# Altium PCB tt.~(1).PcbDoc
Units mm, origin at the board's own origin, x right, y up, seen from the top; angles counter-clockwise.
Board outline 69.6 x 32 mm, 2 copper layers (Top Layer, Bottom Layer); 13 components, 13 nets, 40 pads, 0 vias.
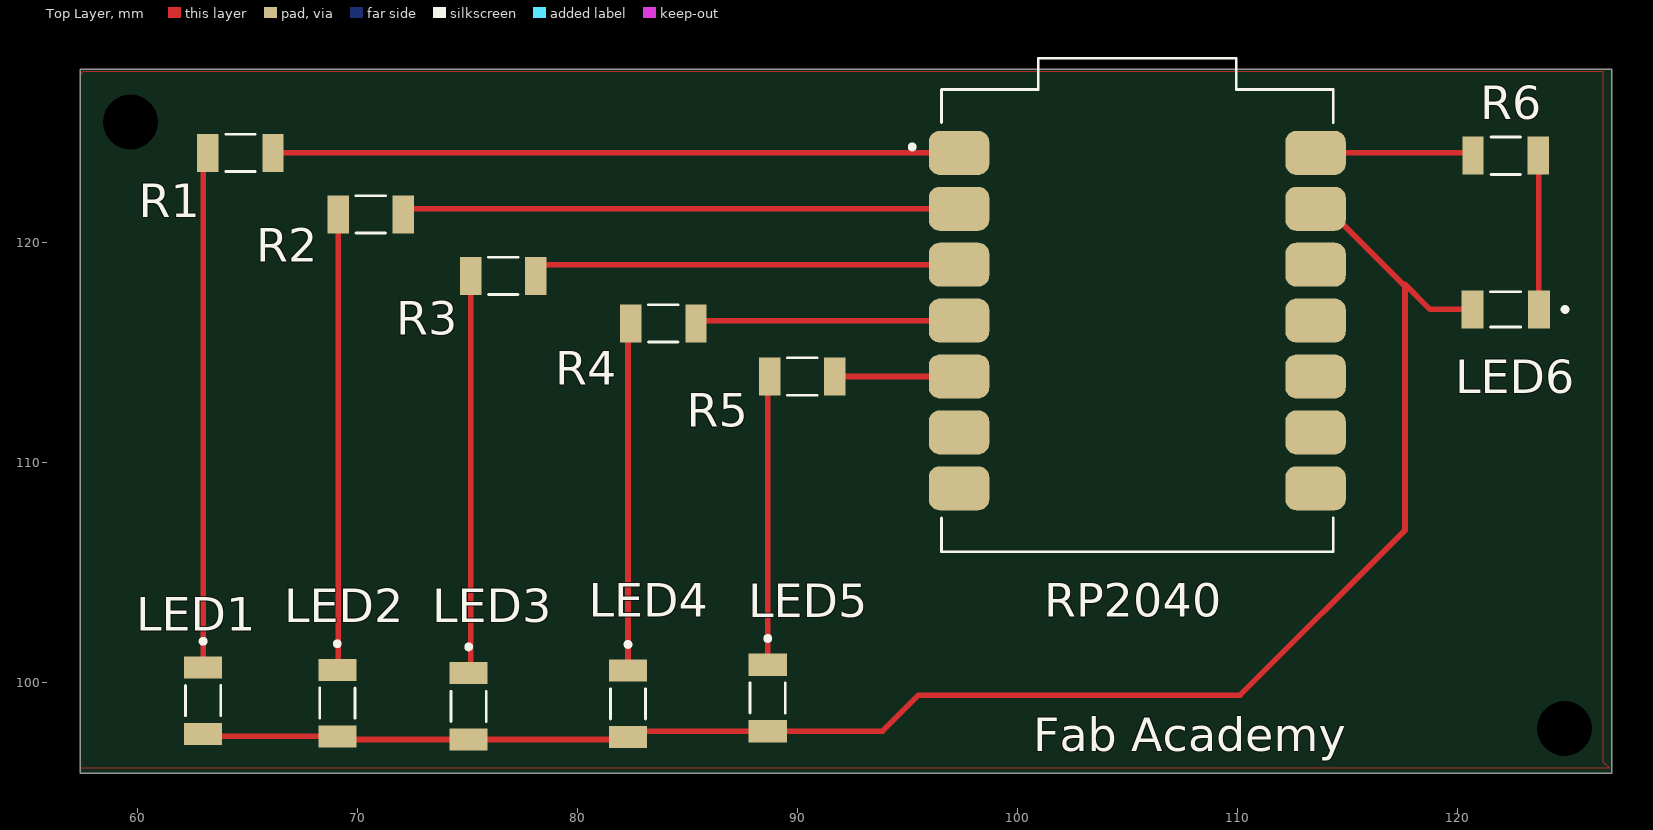
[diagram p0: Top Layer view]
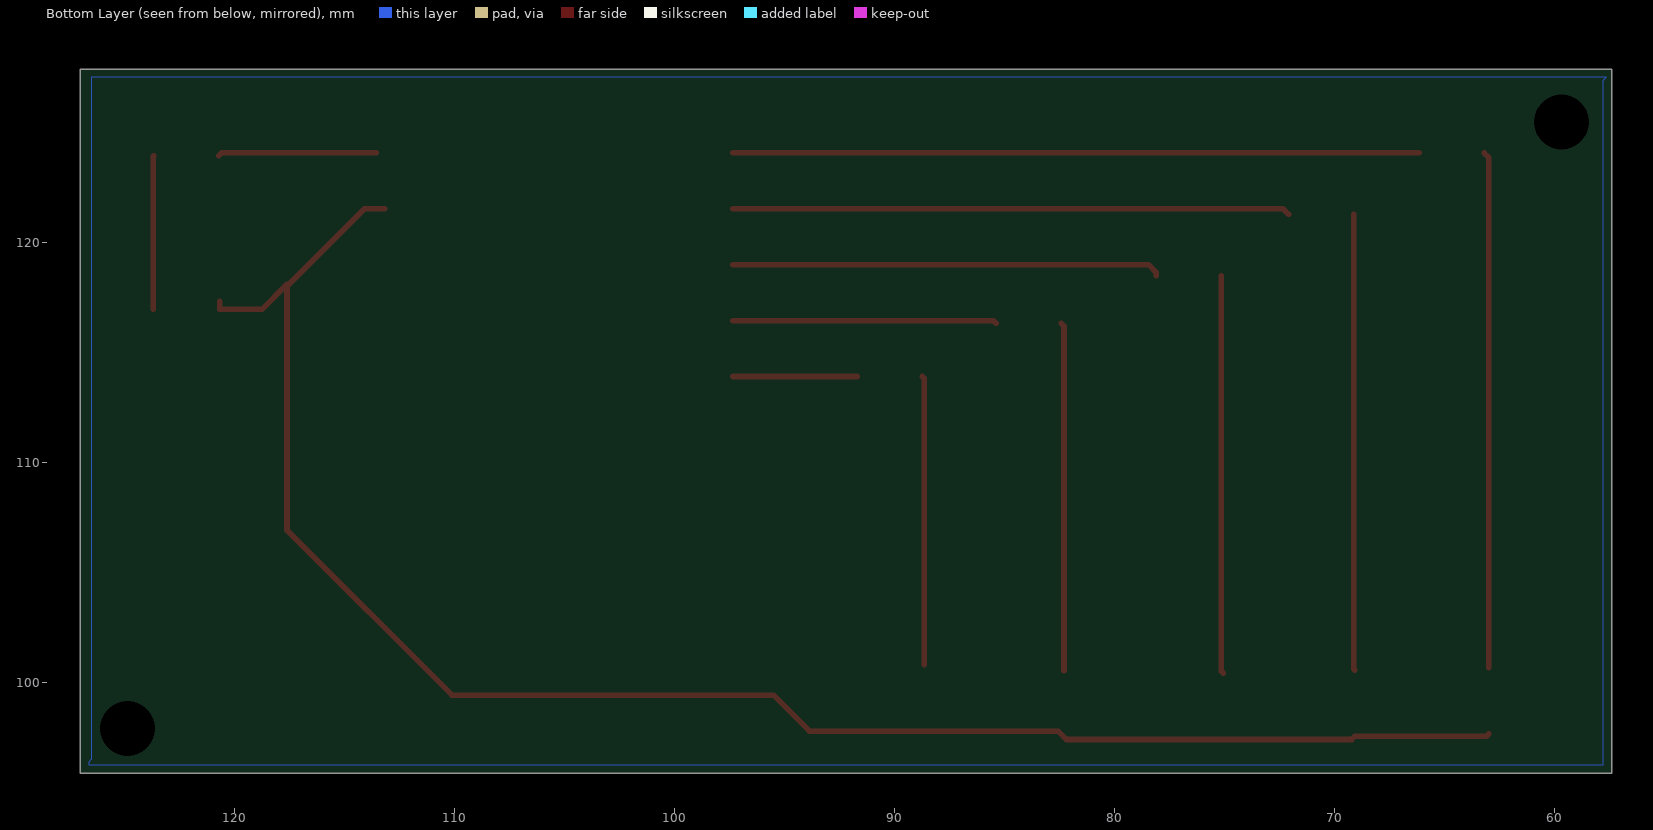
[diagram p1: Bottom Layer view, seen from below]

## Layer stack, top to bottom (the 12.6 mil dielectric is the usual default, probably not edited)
Top Solder: solder mask 0.0102, Solder Resist, Dk 3.5
Top Layer: signal copper 0.0356
Dielectric 1: dielectric 0.32, FR-4, Dk 4.8
Bottom Layer: signal copper 0.0356
Bottom Solder: solder mask 0.0102, Solder Resist, Dk 3.5

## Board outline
57.404,95.885 127,95.885 127,127.889 57.404,127.889

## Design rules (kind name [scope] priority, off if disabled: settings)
AssemblyTestPointUsage [All] p0: scope1count=1 scope1_0_kind=Board scope1_0_value=Board scope2count=1 scope2_0_kind=Board scope2_0_value=Board commentlength=0
AssemblyTestpoint [All] p0: scope1count=1 scope1_0_kind=Board scope1_0_value=Board scope2count=1 scope2_0_kind=Board scope2_0_value=Board commentlength=0
Clearance [All] p0: scope1count=1 scope1_0_kind=Board scope1_0_value=Board scope2count=1 scope2_0_kind=Board scope2_0_value=Board commentlength=0 gap=0.254
Clearance [All] p1: gap=0.254 ignorepadtopadclearanceinfootprint=FALSE except(0: Arc-Hole Track-Hole SMDPad-Hole THPad-Hole Via-Hole Fill-Hole Poly-Hole Region-Hole Text-Hole)
ComponentClearance [All] p0: scope1count=1 scope1_0_kind=Board scope1_0_value=Board scope2count=1 scope2_0_kind=Board scope2_0_value=Board commentlength=0 gap=0.254 collisioncheckmode=3
DiffPairsRouting [All] p0: scope1count=1 scope1_0_kind=Board scope1_0_value=Board scope2count=1 scope2_0_kind=Board scope2_0_value=Board commentlength=0
FabricationTestPointUsage [All] p0: scope1count=1 scope1_0_kind=Board scope1_0_value=Board scope2count=1 scope2_0_kind=Board scope2_0_value=Board commentlength=0 valid=0 allowmultiple=FALSE
FabricationTestpoint [All] p0: scope1count=1 scope1_0_kind=Board scope1_0_value=Board scope2count=1 scope2_0_kind=Board scope2_0_value=Board commentlength=0 side=3 testpointundercomponent=TRUE minsize=1.016 maxsize=2.54 preferedsize=1.524 minholesize=0 maxholesize=1.016 preferedholesize=0.813 testpointgrid=0.025
FanoutControl Fanout_BGA [All] p0 off: scope1count=1 scope1_0_kind=Board scope1_0_value=Board scope2count=1 scope2_0_kind=Board scope2_0_value=Board commentlength=69 // Protel DXP Scope 1 Expression Was: IsBGA   Fanout_BGA (Default Rule)
FanoutControl Fanout_LCC [All] p0 off: scope1count=1 scope1_0_kind=Board scope1_0_value=Board scope2count=1 scope2_0_kind=Board scope2_0_value=Board commentlength=69 // Protel DXP Scope 1 Expression Was: IsLCC   Fanout_LCC (Default Rule)
FanoutControl Fanout_SOIC [All] p0 off: scope1count=1 scope1_0_kind=Board scope1_0_value=Board scope2count=1 scope2_0_kind=Board scope2_0_value=Board commentlength=71 // Protel DXP Scope 1 Expression Was: IsSOIC   Fanout_SOIC (Default Rule)
FanoutControl Fanout_Small [All] p0 off: scope1count=1 scope1_0_kind=Board scope1_0_value=Board scope2count=1 scope2_0_kind=Board scope2_0_value=Board commentlength=84 // Protel DXP Scope 1 Expression Was: (CompPinCount < 5)   Fanout_Small (Default Rule)
FanoutControl Fanout_Default [All] p0: scope1count=1 scope1_0_kind=Board scope1_0_value=Board scope2count=1 scope2_0_kind=Board scope2_0_value=Board commentlength=30 // Fanout_Default (Default Rule)
Height [All] p0: scope1count=1 scope1_0_kind=Board scope1_0_value=Board scope2count=1 scope2_0_kind=Board scope2_0_value=Board commentlength=0
HoleSize [All] p0: scope1count=1 scope1_0_kind=Board scope1_0_value=Board scope2count=1 scope2_0_kind=Board scope2_0_value=Board commentlength=0 absolutevalues=TRUE maxlimit=2.54 minlimit=0.025 maxpercent=80.000 minpercent=20.000
HoleToHoleClearance [All] p0: scope1count=1 scope1_0_kind=Board scope1_0_value=Board scope2count=1 scope2_0_kind=Board scope2_0_value=Board commentlength=0
LayerPairs [All] p0: scope1count=1 scope1_0_kind=Board scope1_0_value=Board scope2count=1 scope2_0_kind=Board scope2_0_value=Board commentlength=0 enforce=TRUE
MinimumSolderMaskSliver [All] p0: scope1count=1 scope1_0_kind=Board scope1_0_value=Board scope2count=1 scope2_0_kind=Board scope2_0_value=Board commentlength=0
NetAntennae [All] p0: scope1count=1 scope1_0_kind=Board scope1_0_value=Board scope2count=1 scope2_0_kind=Board scope2_0_value=Board commentlength=0
PasteMaskExpansion [All] p0: scope1count=1 scope1_0_kind=Board scope1_0_value=Board scope2count=1 scope2_0_kind=Board scope2_0_value=Board commentlength=0 expansion=0
PlaneClearance [All] p0: scope1count=1 scope1_0_kind=Board scope1_0_value=Board scope2count=1 scope2_0_kind=Board scope2_0_value=Board commentlength=0 clearance=0.508
PlaneConnect [All] p0: scope1count=1 scope1_0_kind=Board scope1_0_value=Board scope2count=1 scope2_0_kind=Board scope2_0_value=Board commentlength=0 planeconnectstyle=Relief reliefexpansion=0.508 reliefentries=4 reliefconductorwidth=0.254 reliefairgap=0.254
PolygonConnect [All] p0: scope1count=1 scope1_0_kind=Board scope1_0_value=Board scope2count=1 scope2_0_kind=Board scope2_0_value=Board commentlength=0 connectstyle=Relief reliefconductorwidth=0.254 reliefentries=4 polygonreliefangle="90 Angle"
PolygonConnect [All] p1: connectstyle=Relief reliefconductorwidth=0.254 reliefentries=4 polygonreliefangle="90 Angle" airgapwidth=0.254
RoutingCorners [All] p0: scope1count=1 scope1_0_kind=Board scope1_0_value=Board scope2count=1 scope2_0_kind=Board scope2_0_value=Board commentlength=0 cornerstyle=45-Degree minsetback=2.54 maxsetback=2.54
RoutingLayers [All] p0: scope1count=1 scope1_0_kind=Board scope1_0_value=Board scope2count=1 scope2_0_kind=Board scope2_0_value=Board commentlength=0 top layer=Automatic bottom layer=Automatic
RoutingPriority [All] p0: scope1count=1 scope1_0_kind=Board scope1_0_value=Board scope2count=1 scope2_0_kind=Board scope2_0_value=Board commentlength=0
RoutingTopology [All] p0: scope1count=1 scope1_0_kind=Board scope1_0_value=Board scope2count=1 scope2_0_kind=Board scope2_0_value=Board commentlength=0 topology=Shortest
RoutingVias [All] p0: scope1count=1 scope1_0_kind=Board scope1_0_value=Board scope2count=1 scope2_0_kind=Board scope2_0_value=Board commentlength=0 holewidth=0.711 width=1.27 viastyle="Through Hole" minholewidth=0.711 minwidth=1.27 maxholewidth=0.711 maxwidth=1.27
RoutingVias [All] p1: holewidth=0.711 width=1.27 viastyle="Through Hole" minholewidth=0.711 minwidth=1.27 maxholewidth=0.711 maxwidth=1.27
ShortCircuit [All] p0: scope1count=1 scope1_0_kind=Board scope1_0_value=Board scope2count=1 scope2_0_kind=Board scope2_0_value=Board commentlength=0 allowed=FALSE
SilkToBoardRegionClearance [All] p0: scope1count=1 scope1_0_kind=Board scope1_0_value=Board scope2count=1 scope2_0_kind=Board scope2_0_value=Board commentlength=0
SilkToSilkClearance [All] p0: scope1count=1 scope1_0_kind=Board scope1_0_value=Board scope2count=1 scope2_0_kind=Board scope2_0_value=Board commentlength=0
SilkToSolderMaskClearance [All] p0 off: scope1count=1 scope1_0_kind=Board scope1_0_value=Board scope2count=1 scope2_0_kind=Board scope2_0_value=Board commentlength=44 // Protel DXP Scope 1 Expression Was: IsPad
SolderMaskExpansion [All] p0: scope1count=1 scope1_0_kind=Board scope1_0_value=Board scope2count=1 scope2_0_kind=Board scope2_0_value=Board commentlength=0 expansion=0.102
SolderMaskExpansion [All] p1: expansion=0.102 istentingtop=FALSE
UnRoutedNet [All] p0: scope1count=1 scope1_0_kind=Board scope1_0_value=Board scope2count=1 scope2_0_kind=Board scope2_0_value=Board commentlength=0
UnpouredPolygon [All] p0: scope1count=1 scope1_0_kind=Board scope1_0_value=Board scope2count=1 scope2_0_kind=Board scope2_0_value=Board commentlength=0
Width [All] p0: scope1count=1 scope1_0_kind=Board scope1_0_value=Board scope2count=1 scope2_0_kind=Board scope2_0_value=Board commentlength=0 maxlimit=0.254 minlimit=0.254 preferedwidth=0.254
Width [All] p1: maxlimit=0.254 minlimit=0.254 preferedwidth=0.254
30 further rules are at their usual default settings.

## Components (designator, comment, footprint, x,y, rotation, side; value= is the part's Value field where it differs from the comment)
LED1 "LHN974_RED_LED_1206" LED2 62.992,99.187 r270 top
LED2 "LHN974_RED_LED_1206" LED2 69.088,99.074 r270 top
LED3 "LHN974_RED_LED_1206" LED2 75.057,98.933 r270 top
LED4 "LHN974_RED_LED_1206" LED2 82.296,99.046 r270 top
LED5 "LHN974_RED_LED_1206" LED2 88.646,99.314 r270 top
LED6 "LHN974_RED_LED_1206" LED2 122.174,116.967 r180 top
R1 "1k" 1k 64.687,124.079 r0 top
R2 "1k" 1k 70.612,121.285 r0 top
R3 "1k" 1k 76.625,118.491 r0 top
R4 "1k" 1k 83.903,116.332 r0 top
R5 "1k" 1k 90.214,113.919 r0 top
R6 "1k" 1k 122.174,123.952 r0 top
RP2040 "" 102010428 105.438,116.459 r0 top

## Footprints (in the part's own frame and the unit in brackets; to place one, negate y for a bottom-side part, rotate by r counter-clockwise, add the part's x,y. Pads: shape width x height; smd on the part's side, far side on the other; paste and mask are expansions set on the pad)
1k [mm]
  rect 0.97x1.73 smd: 1(-1.48,0) 2(1.48,0)
  silkscreen extent -0.67,-0.85 0.67,0.85
102010428 [mm]
  rrect50% 2.75x2 smd: 1(-8.1,7.62) 2(-8.1,5.08) 3(-8.1,2.54) 4(-8.1,0) 5(-8.1,-2.54) 6(-8.1,-5.08) 7(-8.1,-7.62) 8(8.1,-7.62) 9(8.1,-5.08) 10(8.1,-2.54) 11(8.1,0) 12(8.1,2.54) 13(8.1,5.08) 14(8.1,7.62)
  silkscreen extent -10.33,-10.5 8.9,11.92
LED2 [mm] "LEDC3216X120N"
  rect 1.01x1.73 smd: NEG(1.51,0) POS(-1.51,0)
  silkscreen extent -2.8,-0.8 0.68,0.8

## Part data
LED1 LED2 LED3 LED4 LED5 LED6: library part LED2, "2.6 V Red LED SMD"
R1 R2 R3 R4 R5 R6: "Res Thick Film 3.2 x 1.6 mm 6.8K Ohm 1% 0.25W(1/4W) 100ppm/ C Molded SMD Paper T/R"
RP2040: library part 102010428, "RP2040 XIAO RP2040 series ARM® Cortex®-M0+ MCU 32-Bit Embedded Evaluation Board"

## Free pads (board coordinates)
  round 1.524 hole 2.5: 7(59.69,125.476) 8(124.841,97.917)

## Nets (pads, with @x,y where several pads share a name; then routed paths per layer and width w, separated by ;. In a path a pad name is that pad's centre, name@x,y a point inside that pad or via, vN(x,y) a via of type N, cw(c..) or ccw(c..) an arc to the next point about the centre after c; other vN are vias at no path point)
GND: LED1.NEG LED2.NEG LED3.NEG LED4.NEG LED5.NEG LED6.NEG RP2040.13 | length 79.6
  Top Layer w0.254: LED1.NEG 63.105,97.564 LED2.NEG 69.229,97.423 LED3.NEG 82.183,97.423 LED4.NEG 82.564,97.804 LED5.NEG 93.867,97.804 95.504,99.441 110.109,99.441 117.602,106.934 117.602,118.11 ; RP2040.13@113.163,121.539 RP2040.13 114.079,121.539 117.508,118.11 117.602,118.11 ; LED6.NEG@120.664,117.327 LED6.NEG 118.745,116.967 117.602,118.11
NetLED1_POS: LED1.POS R1.1 | length 23.5
  Top Layer w0.254: LED1.POS 62.992,123.864 R1.1
NetLED2_POS: LED2.POS R2.1 | length 20.7
  Top Layer w0.254: LED2.POS 69.132,100.628 R2.1
NetLED3_POS: LED3.POS R3.1 | length 18.1
  Top Layer w0.254: LED3.POS 75.145,100.531 R3.1
NetLED4_POS: LED4.POS R4.1 | length 15.8
  Top Layer w0.254: LED4.POS 82.296,116.205 R4.1
NetLED5_POS: LED5.POS R5.1 | length 13.1
  Top Layer w0.254: LED5.POS 88.646,113.831 R5.1
NetLED6_POS: LED6.POS R6.2 | length 7
  Top Layer w0.254: R6.2 123.684,123.922 LED6.POS
NetR1_2: R1.2 RP2040.1 | length 31.2
  Top Layer w0.254: R1.2 RP2040.1
NetR2_2: R2.2 RP2040.2 | length 25.4
  Top Layer w0.254: R2.2 72.346,121.539 RP2040.2
NetR3_2: R3.2 RP2040.3 | length 19.5
  Top Layer w0.254: R3.2 78.105,118.641 78.463,118.999 RP2040.3
NetR4_2: R4.2 RP2040.4 | length 12
  Top Layer w0.254: R4.2 85.51,116.459 RP2040.4
NetR5_2: R5.2 RP2040.5 | length 5.6
  Top Layer w0.254: R5.2 RP2040.5
NetR6_1: R6.1 RP2040.14 | length 7.2
  Top Layer w0.254: RP2040.14 120.567,124.079 R6.1
pads on no net: RP2040.6 RP2040.7 RP2040.8 RP2040.9 RP2040.10 RP2040.11 RP2040.12

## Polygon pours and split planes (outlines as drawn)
no net on Bottom Layer "NONET_L02_P000" (solid, pour order 0): 126.619,96.266 57.785,96.266 57.785,127.381 57.658,127.508 126.492,127.508 126.492,96.52 126.619,96.393
GND on Top Layer "gnd" (solid, remove dead copper, pour order 2): 126.619,127.762 57.531,127.762 57.404,127.635 57.404,96.139 126.873,96.139 126.619,96.393

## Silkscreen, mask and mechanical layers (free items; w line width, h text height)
Top Overlay:
  text "Fab Academy" at 100.711,96.901 h1.52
